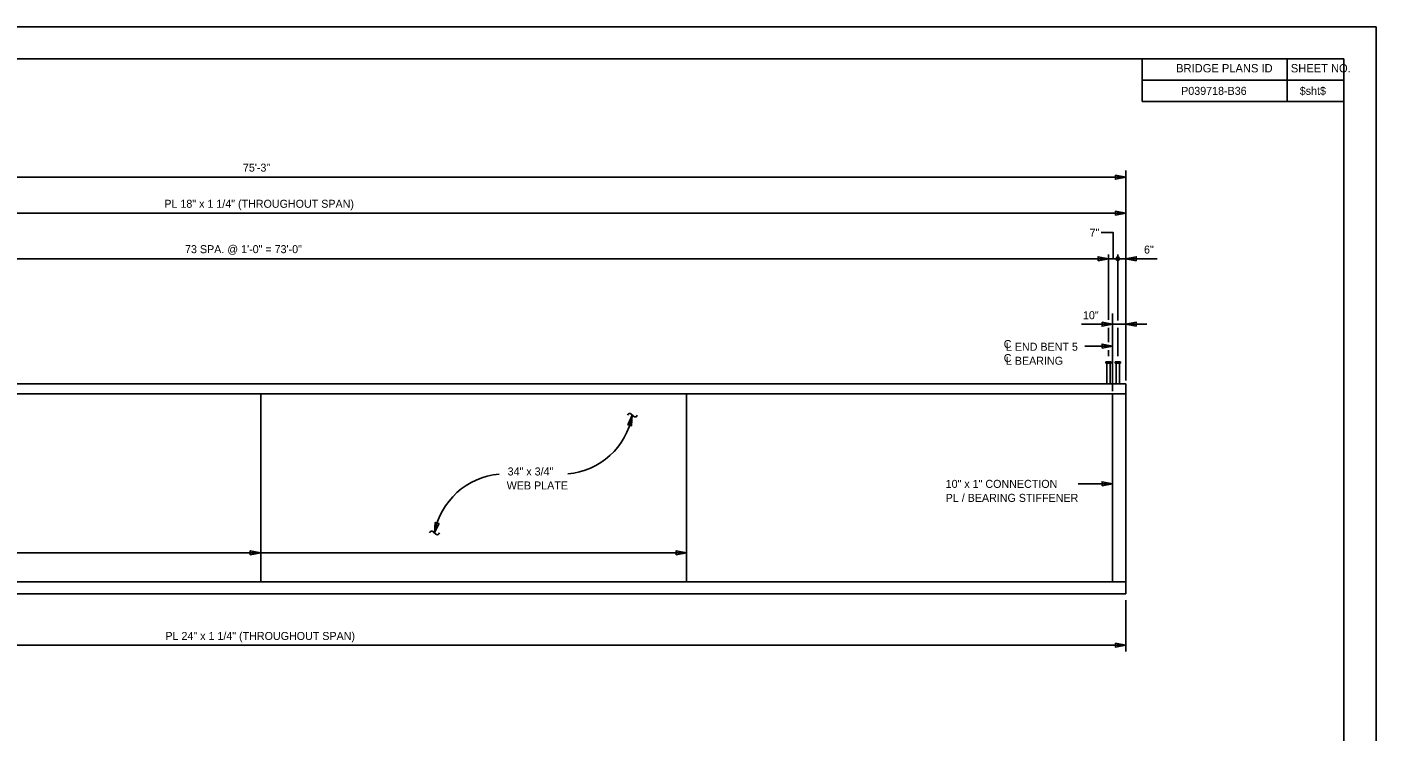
# Model space of a CAD drawing. Extents: x -305 to -161, y -187 to -99.
# Drawn here: x -245.4 to -161.2, y -143.5 to -99.5 of the extents above; entities that cross this region are included whole.
import ezdxf

# ---------------------------------------------------------------- set-up
doc = ezdxf.new("R2010")
doc.units = 0
for name, color, linetype in [('BR_AUTO DIMENSION', 7, 'Continuous'), ('BR_BORDER LINES', 7, 'Continuous'), ('BR_CENTER LINES', 7, 'Continuous'), ('BR_STRUCTURAL STEEL', 7, 'Continuous'), ('BR_TEXT', 7, 'Continuous'), ('Default', 7, 'Continuous'), ('Level 31', 7, 'Continuous')]:
    doc.layers.add(name, color=color, linetype=linetype)

msp = doc.modelspace()

# ---------------------------------------------------------------- linework, layer by layer
at = {"layer": 'BR_AUTO DIMENSION'}
for p, q in [((-176.804, -121.593), (-176.804, -108.463)), ((-284.888, -108.876), (-176.804, -108.876)), ((-284.888, -111.134), (-176.804, -111.134)), ((-177.888, -117.796), (-177.888, -113.71)), ((-177.304, -117.843), (-177.304, -113.71)), ((-177.888, -113.971), (-283.721, -113.971)), ((-174.851, -113.971), (-177.888, -113.971)), ((-179.584, -118.071), (-175.498, -118.071)), ((-177.888, -119.179), (-177.888, -118.298)), ((-177.304, -120.06), (-177.304, -118.298)), ((-177.638, -119.433), (-179.361, -119.433)), ((-177.888, -120.06), (-177.888, -119.697)), ((-177.638, -128.037), (-179.782, -128.037)), ((-204.242, -132.351), (-288.443, -132.351)), ((-176.804, -135.312), (-176.804, -138.518)), ((-284.888, -138.117), (-176.804, -138.117))]:
    msp.add_line(p, q, dxfattribs=at)
for points in [[(-177.454, -108.751), (-176.804, -108.876), (-177.454, -109.001)], [(-177.454, -111.259), (-176.804, -111.134), (-177.454, -111.009)], [(-178.538, -114.096), (-177.888, -113.971), (-178.538, -113.846)], [(-176.154, -114.096), (-176.804, -113.971), (-176.154, -113.846)], [(-178.288, -117.946), (-177.638, -118.071), (-178.288, -118.196)], [(-176.154, -118.196), (-176.804, -118.071), (-176.154, -117.946)], [(-178.288, -119.558), (-177.638, -119.433), (-178.288, -119.308)], [(-207.919, -124.344), (-207.636, -123.746), (-207.676, -124.406)], [(-178.288, -128.162), (-177.638, -128.037), (-178.288, -127.912)], [(-219.705, -130.513), (-219.987, -131.111), (-219.947, -130.451)], [(-231.496, -132.476), (-230.846, -132.351), (-231.496, -132.226)], [(-204.892, -132.476), (-204.242, -132.351), (-204.892, -132.226)], [(-177.454, -137.992), (-176.804, -138.117), (-177.454, -138.242)]]:
    msp.add_lwpolyline(points, close=True, dxfattribs=at)
msp.add_lwpolyline([(-177.596, -113.971), (-177.596, -112.325), (-178.336, -112.325)], dxfattribs=at)
msp.add_circle((-177.304, -113.971), 0.111, dxfattribs=at)
for centre, start, end in [((-212.06, -122.942), 274.96239, 349.7037), ((-215.563, -131.915), 94.96239, 169.7037)]:
    msp.add_arc(centre, 4.497, start, end, dxfattribs=at)
at = {"layer": 'BR_BORDER LINES'}
for p, q in [((-163.178, -101.489), (-297.843, -101.489)), ((-175.788, -104.156), (-175.788, -101.489)), ((-166.722, -104.156), (-166.722, -101.489)), ((-163.178, -185.489), (-163.178, -101.489)), ((-175.788, -102.808), (-163.178, -102.808)), ((-166.722, -102.808), (-163.178, -102.808)), ((-163.178, -104.156), (-175.788, -104.156))]:
    msp.add_line(p, q, dxfattribs=at)
at = {"layer": 'BR_CENTER LINES'}
msp.add_line((-177.638, -117.387), (-177.638, -122.256), dxfattribs=at)
at = {"layer": 'BR_STRUCTURAL STEEL'}
for p, q in [((-284.888, -121.787), (-176.804, -121.787)), ((-176.804, -121.787), (-176.804, -122.412)), ((-284.888, -122.412), (-176.804, -122.412)), ((-230.846, -122.412), (-230.846, -134.162)), ((-204.242, -122.412), (-204.242, -134.162)), ((-177.638, -122.412), (-177.638, -134.162)), ((-176.804, -122.412), (-176.804, -134.162)), ((-284.888, -134.162), (-176.804, -134.162)), ((-176.804, -134.162), (-176.804, -134.912)), ((-284.888, -134.912), (-176.804, -134.912))]:
    msp.add_line(p, q, dxfattribs=at)
at = {"layer": 'BR_TEXT'}
for p, q in [((-207.896, -123.693), (-207.938, -123.754)), ((-207.554, -123.82), (-207.717, -123.671)), ((-207.321, -123.754), (-207.351, -123.8)), ((-220.302, -131.103), (-220.272, -131.057)), ((-220.069, -131.037), (-219.906, -131.186)), ((-219.727, -131.164), (-219.685, -131.103))]:
    msp.add_line(p, q, dxfattribs=at)
for centre, radius, start, end in [((-207.798, -123.746), 0.111, 43.45189, 151.73747), ((-207.461, -123.739), 0.125, 221.00704, 330.80591), ((-220.163, -131.118), 0.125, 41.00704, 150.80591), ((-219.825, -131.111), 0.111, 223.45189, 331.73747)]:
    msp.add_arc(centre, radius, start, end, dxfattribs=at)
at = {"layer": 'Default'}
for p, q in [((-178.059, -120.412), (-178.059, -120.506)), ((-178.059, -120.412), (-177.716, -120.412)), ((-178.059, -120.506), (-177.716, -120.506)), ((-177.997, -120.506), (-177.997, -121.787)), ((-177.778, -120.506), (-177.778, -121.787)), ((-177.716, -120.412), (-177.716, -120.506)), ((-177.476, -120.412), (-177.476, -120.506)), ((-177.476, -120.412), (-177.132, -120.412)), ((-177.476, -120.506), (-177.132, -120.506)), ((-177.414, -120.506), (-177.414, -121.787)), ((-177.195, -120.506), (-177.195, -121.787)), ((-177.132, -120.412), (-177.132, -120.506))]:
    msp.add_line(p, q, dxfattribs=at)
at = {"layer": 'Level 31'}
msp.add_lwpolyline([(-305.176, -187.489), (-161.176, -187.489), (-161.176, -99.489), (-305.176, -99.489)], close=True, dxfattribs=at)

# ---------------------------------------------------------------- texts
at = {"layer": 'BR_AUTO DIMENSION'}
for s, p in [('75\'-3"', (-231.958, -108.53)), ('PL 18" x 1 1/4" (THROUGHOUT SPAN)', (-236.867, -110.788)), ('7"', (-179.068, -112.593)), ('73 SPA. @ 1\'-0" = 73\'-0"', (-235.574, -113.625)), ('6"', (-175.669, -113.652)), ('10"', (-179.482, -117.752)), ('34" x 3/4" ', (-215.422, -127.518)), ('WEB PLATE', (-215.48, -128.393)), ('PL 24" x 1 1/4" (THROUGHOUT SPAN)', (-236.8, -137.798))]:
    msp.add_text(s, height=0.5, rotation=360, dxfattribs=at).set_placement(p)
at = {"layer": 'BR_TEXT'}
for s, height, p in [('BRIDGE PLANS ID', 0.52, (-173.663, -102.327)), ('SHEET NO.', 0.52, (-166.499, -102.327)), ('P039718-B36', 0.5, (-173.348, -103.732)), ('$sht$', 0.5, (-165.939, -103.732))]:
    msp.add_text(s, height=height, dxfattribs=at).set_placement(p)
for s, p in [('C', (-184.431, -119.556)), ('L END BENT 5', (-184.296, -119.723)), ('C', (-184.431, -120.431)), ('L BEARING', (-184.296, -120.598)), ('10" x 1" CONNECTION ', (-188.059, -128.293)), ('PL / BEARING STIFFENER', (-188.059, -129.168))]:
    msp.add_text(s, height=0.5, rotation=360, dxfattribs=at).set_placement(p)

doc.saveas('drawing.dxf')
